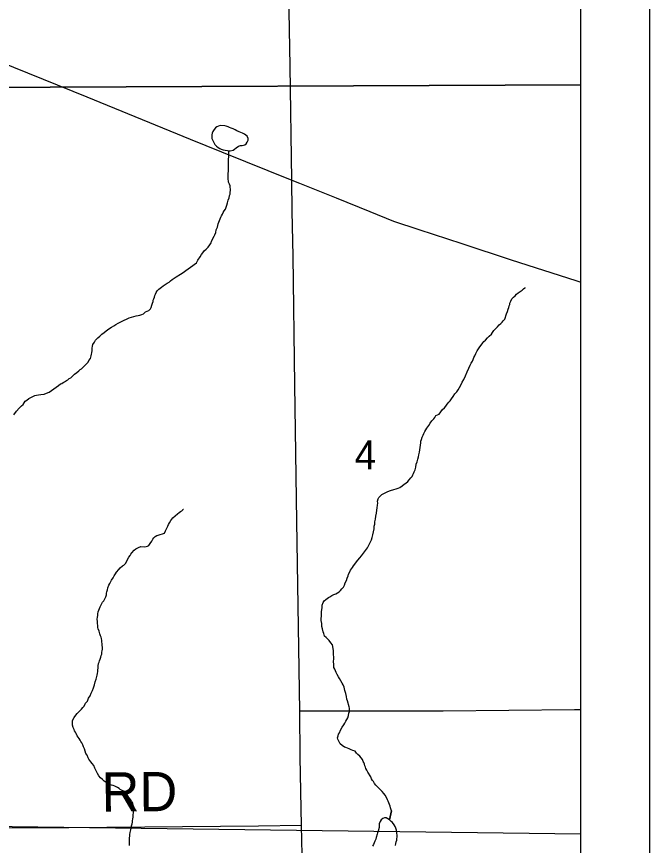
# Model space of a CAD drawing. Extents: x 10.6 to 44.6, y -2.6 to 23.4.
# Drawn here: x 19.186 to 20.103, y 16.584 to 17.784 of the extents above; entities that cross this region are included whole.
import ezdxf

# ---------------------------------------------------------------- set-up
doc = ezdxf.new("R2010")
doc.units = 0
for name, color, linetype in [('GM_X_County', 7, 'Continuous'), ('GM_X_County_Road', 7, 'Continuous'), ('GM_X_Minor_Lake', 7, 'Continuous'), ('GM_X_Minor_River', 7, 'Continuous'), ('GM_X_Section', 7, 'Continuous'), ('GM_X_Section_Text', 7, 'Continuous'), ('GM_X_Township', 7, 'Continuous'), ('GM_X_Township_Road', 7, 'Continuous'), ('GM_X_Township_Road_Text', 7, 'Continuous'), ('GM_X_US_Route', 7, 'Continuous'), ('SH_Data', 7, 'Continuous')]:
    doc.layers.add(name, color=color, linetype=linetype)

msp = doc.modelspace()

# ---------------------------------------------------------------- linework, layer by layer
at = {"layer": 'GM_X_County'}
msp.add_lwpolyline([(20.0033, 15.5302), (20.0033, 22.3267), (13.2033, 22.3267), (13.2033, 15.5267), (19.8413, 15.5267)], dxfattribs=at)
at = {"layer": 'GM_X_County_Road'}
for points in [[(19.5848, 17.5467), (19.5826, 17.712), (19.5792, 17.8983), (19.5753, 18.0763), (19.5711, 18.2524), (19.5677, 18.4449), (19.5648, 18.6461), (19.5616, 18.8476), (19.5588, 19.0263)], [(19.6248, 15.5267), (19.6234, 15.5414), (19.6215, 15.6293), (19.6203, 15.7403), (19.6182, 15.8416), (19.6161, 15.9391), (19.614, 16.0288), (19.6109, 16.1339), (19.6094, 16.1895), (19.6059, 16.3321), (19.6008, 16.5277), (19.5991, 16.6126), (19.5971, 16.7116), (19.5964, 16.7781), (19.5922, 17.0526), (19.589, 17.2507), (19.5866, 17.4368), (19.5856, 17.5019), (19.5848, 17.5467)]]:
    msp.add_lwpolyline(points, dxfattribs=at)
at = {"layer": 'GM_X_Minor_Lake'}
for points in [[(19.481, 17.6263), (19.4765, 17.624), (19.4742, 17.6225), (19.4724, 17.6202), (19.4705, 17.6175), (19.4697, 17.6152), (19.469, 17.6126), (19.469, 17.6085)], [(19.469, 17.6085), (19.469, 17.6072), (19.4698, 17.6053), (19.471, 17.6034), (19.4717, 17.6016), (19.4733, 17.5985), (19.4756, 17.5963), (19.4783, 17.594), (19.4805, 17.5929), (19.4824, 17.5918), (19.4855, 17.5906), (19.4881, 17.5903), (19.4916, 17.5899), (19.4935, 17.5896), (19.4954, 17.5896), (19.4999, 17.5904), (19.5018, 17.5919), (19.5044, 17.5938), (19.5078, 17.5961), (19.5105, 17.5969), (19.5128, 17.5973), (19.5147, 17.5977), (19.5166, 17.5981), (19.5188, 17.5996), (19.5203, 17.6019), (19.5218, 17.6046), (19.5218, 17.6072), (19.5203, 17.6106), (19.5183, 17.6122), (19.5161, 17.6133), (19.5134, 17.6148), (19.5111, 17.6159), (19.5088, 17.617), (19.5054, 17.6185), (19.5027, 17.6196), (19.4997, 17.6211), (19.497, 17.6223), (19.4947, 17.6234), (19.4928, 17.6241), (19.4898, 17.6249), (19.488, 17.6254)], [(19.488, 17.6254), (19.481, 17.6263)], [(19.7349, 16.5837), (19.7353, 16.5864), (19.736, 16.589), (19.7368, 16.5913), (19.7372, 16.5936), (19.7375, 16.5963), (19.7375, 16.599), (19.7371, 16.6012), (19.7371, 16.6035), (19.7363, 16.6058), (19.7355, 16.6089), (19.7344, 16.6111), (19.7332, 16.6138), (19.7309, 16.6168), (19.7286, 16.6187), (19.7263, 16.621), (19.7237, 16.6225), (19.7214, 16.6236), (19.7191, 16.624), (19.7168, 16.6229), (19.7142, 16.6209), (19.7127, 16.6183), (19.7116, 16.6152), (19.7116, 16.6125), (19.7112, 16.6099), (19.7098, 16.6045), (19.709, 16.6022), (19.7086, 16.6), (19.7072, 16.5954), (19.7064, 16.5931), (19.7049, 16.59), (19.7042, 16.5874), (19.7031, 16.5851), (19.7016, 16.5828)]]:
    msp.add_lwpolyline(points, dxfattribs=at)
at = {"layer": 'GM_X_Minor_River'}
for points in [[(19.447, 17.4273), (19.4487, 17.4312), (19.4521, 17.4357), (19.454, 17.4392), (19.4559, 17.4418), (19.4581, 17.4445), (19.4608, 17.4472), (19.4638, 17.4499), (19.466, 17.4533), (19.4679, 17.4564), (19.4687, 17.4583), (19.4705, 17.4625), (19.4724, 17.4659), (19.4735, 17.4678), (19.4746, 17.4712), (19.4754, 17.475), (19.4765, 17.477), (19.4772, 17.4789), (19.4783, 17.4838), (19.482, 17.4933), (19.4832, 17.4952), (19.4843, 17.4975), (19.4854, 17.5002), (19.4869, 17.5025), (19.4888, 17.5048), (19.4899, 17.5078), (19.4906, 17.5109), (19.4918, 17.5139), (19.4929, 17.5181), (19.494, 17.5215), (19.4947, 17.5246), (19.4955, 17.5265), (19.4954, 17.5295), (19.4962, 17.5318), (19.4962, 17.5337), (19.4958, 17.5368), (19.4954, 17.5386), (19.4946, 17.5413), (19.4934, 17.544), (19.493, 17.5462), (19.4926, 17.5481), (19.4935, 17.5896)], [(19.296, 17.3066), (19.2967, 17.3089), (19.2989, 17.3124), (19.3003, 17.3155), (19.3037, 17.3186), (19.3067, 17.3213), (19.3097, 17.3241), (19.313, 17.3264), (19.316, 17.3288), (19.3198, 17.3315), (19.3235, 17.3339), (19.3269, 17.3359), (19.3299, 17.3378), (19.3336, 17.3398), (19.3363, 17.3414), (19.3393, 17.3426), (19.3419, 17.3442), (19.3453, 17.3458), (19.3491, 17.3474), (19.3525, 17.3486), (19.3562, 17.3495), (19.3593, 17.3503), (19.3623, 17.3511), (19.3649, 17.3516), (19.3676, 17.3524), (19.3702, 17.3536), (19.3728, 17.3563), (19.3755, 17.3575), (19.3777, 17.3583), (19.3803, 17.3607), (19.381, 17.3626), (19.3821, 17.366), (19.3832, 17.3691), (19.3839, 17.3714), (19.3842, 17.3733), (19.3849, 17.3752), (19.386, 17.3775), (19.3867, 17.3798), (19.3874, 17.3821), (19.3885, 17.3844), (19.39, 17.3868), (19.3922, 17.3891), (19.3941, 17.3907), (19.396, 17.3922), (19.3986, 17.3938), (19.4016, 17.3958), (19.4042, 17.3977), (19.4072, 17.3993), (19.4094, 17.4013), (19.4117, 17.4032), (19.4147, 17.4052), (19.4173, 17.4068), (19.4196, 17.4084), (19.4214, 17.4092), (19.4237, 17.4107), (19.4259, 17.4123), (19.447, 17.4273)], [(19.7806, 17.188), (19.7821, 17.19), (19.7835, 17.1919), (19.785, 17.1953), (19.7876, 17.1985), (19.7905, 17.2016), (19.792, 17.2035), (19.7935, 17.2062), (19.7961, 17.2074), (19.7984, 17.2082), (19.8032, 17.2148), (19.8062, 17.2175), (19.808, 17.2198), (19.8098, 17.2226), (19.8121, 17.2253), (19.8143, 17.2276), (19.8161, 17.2303), (19.8187, 17.2338), (19.8209, 17.2376), (19.8239, 17.2404), (19.8257, 17.2435), (19.8276, 17.2466), (19.8298, 17.25), (19.8316, 17.2543), (19.8338, 17.2585), (19.8363, 17.2639), (19.8388, 17.2693), (19.8414, 17.2746), (19.8432, 17.2789), (19.8446, 17.282), (19.8465, 17.285), (19.8475, 17.2874), (19.8486, 17.29), (19.8497, 17.2927), (19.8515, 17.2962), (19.8534, 17.2997), (19.8552, 17.3027), (19.857, 17.3055), (19.8589, 17.3082), (19.8614, 17.3116), (19.8629, 17.3136), (19.8652, 17.3152), (19.8681, 17.3186), (19.8707, 17.321), (19.8741, 17.3241), (19.8756, 17.3264), (19.8774, 17.3291), (19.8793, 17.3311), (19.8826, 17.3346), (19.8852, 17.3377), (19.8878, 17.3396), (19.8897, 17.3412), (19.8912, 17.3431), (19.8934, 17.3459), (19.8959, 17.3535), (19.8973, 17.357), (19.898, 17.3604), (19.8991, 17.3627), (19.8998, 17.365), (19.9005, 17.367), (19.9008, 17.3689), (19.9023, 17.3719), (19.9037, 17.375), (19.906, 17.3774), (19.9082, 17.3797), (19.9104, 17.382), (19.9127, 17.384), (19.9157, 17.3859), (19.9183, 17.3875), (19.9205, 17.3895), (19.9224, 17.391), (19.9232, 17.3915)], [(19.1822, 17.2074), (19.1863, 17.2124), (19.19, 17.2167), (19.1934, 17.2202), (19.1956, 17.2221), (19.1971, 17.2245), (19.1989, 17.2268), (19.2012, 17.2284), (19.2038, 17.2307), (19.2109, 17.2343), (19.2128, 17.2351), (19.2151, 17.2355), (19.2181, 17.236), (19.2215, 17.2364), (19.2264, 17.2373), (19.2294, 17.2385), (19.2332, 17.2401), (19.2366, 17.2425), (19.2403, 17.2448), (19.2437, 17.2472), (19.2471, 17.2499), (19.2497, 17.2519), (19.2519, 17.2527), (19.2538, 17.2539), (19.2557, 17.2551), (19.2583, 17.2567), (19.2606, 17.2579), (19.2624, 17.2598), (19.2647, 17.261), (19.2677, 17.2637), (19.2703, 17.2661), (19.2733, 17.2684), (19.2763, 17.2708), (19.2785, 17.2727), (19.2804, 17.2739), (19.2841, 17.2778), (19.2859, 17.2797), (19.2878, 17.2817), (19.2897, 17.2836), (19.2911, 17.2859), (19.2933, 17.2887), (19.2937, 17.2906), (19.2944, 17.2925), (19.2947, 17.2948), (19.2954, 17.2971), (19.2957, 17.3001), (19.2957, 17.302), (19.2957, 17.3039), (19.296, 17.3066)], [(19.6294, 16.8972), (19.6285, 16.901), (19.6281, 16.9052), (19.6276, 16.9094), (19.6275, 16.9124), (19.6278, 16.9158), (19.628, 16.9227), (19.6284, 16.925), (19.6287, 16.9284), (19.629, 16.9319), (19.6304, 16.9353), (19.6319, 16.938), (19.6341, 16.94), (19.636, 16.9411), (19.6382, 16.9427), (19.6401, 16.9439), (19.6427, 16.9455), (19.6457, 16.9471), (19.6484, 16.9483), (19.651, 16.9495), (19.6533, 16.9511), (19.6555, 16.953), (19.6573, 16.9553), (19.6596, 16.9577), (19.661, 16.9604), (19.6621, 16.9638), (19.6639, 16.9673), (19.665, 16.9707), (19.6664, 16.9742), (19.6671, 16.9765), (19.669, 16.98), (19.67, 16.9823), (19.6711, 16.9842), (19.6726, 16.9861), (19.6741, 16.9884), (19.6759, 16.9908), (19.6785, 16.9943), (19.6807, 16.997), (19.6833, 17.0001), (19.6859, 17.0032), (19.6889, 17.007), (19.6914, 17.0109), (19.6944, 17.0148), (19.6966, 17.0186), (19.6984, 17.0225), (19.7002, 17.0263), (19.7013, 17.0298), (19.7023, 17.0336), (19.704, 17.0424), (19.7043, 17.0458), (19.705, 17.0489), (19.7053, 17.0523), (19.706, 17.0562), (19.7067, 17.0607), (19.7073, 17.0649), (19.708, 17.0691), (19.7087, 17.0726), (19.709, 17.0764), (19.7093, 17.0795), (19.7092, 17.0821), (19.7099, 17.0856), (19.711, 17.0875), (19.7132, 17.0898), (19.7151, 17.0918), (19.717, 17.0929), (19.7203, 17.0945), (19.7237, 17.0961), (19.7279, 17.0978), (19.7324, 17.099), (19.7362, 17.1002), (19.7388, 17.1011), (19.7411, 17.1022), (19.7445, 17.1042), (19.7478, 17.1066), (19.7501, 17.1085), (19.7527, 17.1109), (19.7549, 17.1132), (19.7571, 17.1159), (19.759, 17.1179), (19.7601, 17.1202), (19.7612, 17.1221), (19.7623, 17.1248), (19.7633, 17.1275), (19.7644, 17.1313), (19.765, 17.1359), (19.7665, 17.1394), (19.7672, 17.1428), (19.7682, 17.1462), (19.7689, 17.1493), (19.7696, 17.1531), (19.7703, 17.1566), (19.7713, 17.1634), (19.7716, 17.1665), (19.7719, 17.1692), (19.7726, 17.1715), (19.7737, 17.1749), (19.7751, 17.178), (19.7762, 17.1803), (19.7777, 17.183), (19.7791, 17.1853), (19.7806, 17.188)], [(19.3797, 17.0211), (19.3819, 17.0242), (19.3838, 17.0273), (19.3848, 17.0292), (19.3871, 17.0311), (19.3893, 17.0323), (19.3912, 17.0328), (19.4007, 17.036), (19.4021, 17.0391), (19.4028, 17.041), (19.4039, 17.0429), (19.4054, 17.046), (19.4065, 17.0483), (19.4075, 17.051), (19.4098, 17.0541), (19.4127, 17.058), (19.4157, 17.0611), (19.4194, 17.0638), (19.4217, 17.0658), (19.4235, 17.0674), (19.4254, 17.0682), (19.4273, 17.0701), (19.4276, 17.0705), (19.428, 17.0705)], [(19.2695, 16.7518), (19.2683, 16.7548), (19.2674, 16.7578), (19.2673, 16.7627), (19.2673, 16.7646), (19.2698, 16.7689), (19.272, 16.7724), (19.2739, 16.7747), (19.2761, 16.777), (19.2784, 16.779), (19.2802, 16.7813), (19.2821, 16.7833), (19.2839, 16.7856), (19.2861, 16.7898), (19.2891, 16.7929), (19.2905, 16.7971), (19.2927, 16.8006), (19.2945, 16.8045), (19.2963, 16.8083), (19.2978, 16.8122), (19.2992, 16.8164), (19.3002, 16.8206), (19.3013, 16.8244), (19.3023, 16.8282), (19.303, 16.8302), (19.3034, 16.8328), (19.3037, 16.8355), (19.304, 16.8378), (19.3043, 16.8409), (19.3046, 16.8439), (19.3049, 16.847), (19.3057, 16.8493), (19.3064, 16.8512), (19.3075, 16.8535), (19.3082, 16.8562), (19.3089, 16.8588), (19.3096, 16.8608), (19.3099, 16.8634), (19.3102, 16.8657), (19.3106, 16.868), (19.3104, 16.8764), (19.3099, 16.8783), (19.3095, 16.8806), (19.3091, 16.8832), (19.3086, 16.8851), (19.3078, 16.8874), (19.3066, 16.8904), (19.3062, 16.8923), (19.3058, 16.8942), (19.3046, 16.8976), (19.3041, 16.8995), (19.3037, 16.9025), (19.3032, 16.9048), (19.3032, 16.9082), (19.3031, 16.9112), (19.3034, 16.9143), (19.3037, 16.9166), (19.3041, 16.9189), (19.3044, 16.9219), (19.3055, 16.9246), (19.3062, 16.9269), (19.3073, 16.9292), (19.3087, 16.9323), (19.3109, 16.9358), (19.3124, 16.9377), (19.3135, 16.9397), (19.3146, 16.942), (19.3153, 16.9439), (19.3164, 16.9466), (19.3167, 16.9489), (19.317, 16.9511), (19.3177, 16.9538), (19.3184, 16.9569), (19.3198, 16.9607), (19.3213, 16.963), (19.3239, 16.9677), (19.3261, 16.9711), (19.3275, 16.9742), (19.3294, 16.9769), (19.3308, 16.9796), (19.3342, 16.9835), (19.3364, 16.9858), (19.3398, 16.9886), (19.3416, 16.9898), (19.3439, 16.9921), (19.3461, 16.9952), (19.3471, 16.9979), (19.349, 17.001), (19.3508, 17.0037), (19.3519, 17.0056), (19.353, 17.0075), (19.3567, 17.0114), (19.359, 17.013), (19.3608, 17.0142), (19.3627, 17.015), (19.3661, 17.0166), (19.3714, 17.0163), (19.3741, 17.0168), (19.376, 17.0172), (19.3779, 17.018), (19.3797, 17.0211)], [(19.729, 16.6339), (19.7263, 16.621), (19.729, 16.6341), (19.7277, 16.6383), (19.7273, 16.6409), (19.7265, 16.6432), (19.7256, 16.6455), (19.7245, 16.6477), (19.7236, 16.65), (19.7221, 16.653), (19.7201, 16.6564), (19.7181, 16.659), (19.7158, 16.662), (19.713, 16.665), (19.7103, 16.6672), (19.7084, 16.6691), (19.7064, 16.6713), (19.7048, 16.6736), (19.7033, 16.6762), (19.7017, 16.678), (19.7005, 16.6803), (19.6993, 16.6833), (19.695, 16.6901), (19.6934, 16.6927), (19.6922, 16.695), (19.6914, 16.6972), (19.6906, 16.6991), (19.6901, 16.7014), (19.6893, 16.7037), (19.6881, 16.7055), (19.6873, 16.7082), (19.6854, 16.7108), (19.6834, 16.713), (19.6807, 16.7156), (19.6787, 16.7175), (19.6764, 16.7201), (19.673, 16.7212), (19.6706, 16.7223), (19.668, 16.7237), (19.6653, 16.7248), (19.663, 16.7255), (19.661, 16.7262), (19.6576, 16.7285), (19.6549, 16.7311), (19.6537, 16.7329), (19.6525, 16.7356), (19.6513, 16.7378), (19.6512, 16.7397), (19.6519, 16.7424), (19.6526, 16.7447), (19.6537, 16.747), (19.6552, 16.7505), (19.6577, 16.7551), (19.6603, 16.7582), (19.6618, 16.7609), (19.6632, 16.7636), (19.6647, 16.7663), (19.6658, 16.7686), (19.6669, 16.7717), (19.6675, 16.7751), (19.6682, 16.7778), (19.6686, 16.7801), (19.6685, 16.7824), (19.6681, 16.7843), (19.6656, 16.793), (19.6644, 16.7956), (19.6639, 16.7994), (19.6631, 16.8036), (19.6618, 16.8081), (19.6606, 16.813), (19.6594, 16.8164), (19.6578, 16.8187), (19.6558, 16.8221), (19.6538, 16.8254), (19.6523, 16.8281), (19.6507, 16.8315), (19.6491, 16.8341), (19.6479, 16.8367), (19.6471, 16.839), (19.6459, 16.8416), (19.6458, 16.8435), (19.6458, 16.8458), (19.6453, 16.85), (19.6456, 16.8542), (19.6455, 16.8569), (19.6454, 16.8599), (19.6454, 16.8618), (19.6454, 16.8637), (19.6453, 16.866), (19.6449, 16.8686), (19.6444, 16.8717), (19.6436, 16.8743), (19.6416, 16.8773), (19.6389, 16.8807), (19.6369, 16.8822), (19.6346, 16.8848), (19.6323, 16.887), (19.631, 16.8908), (19.6302, 16.8931), (19.6294, 16.8972)], [(19.3498, 16.5838), (19.3497, 16.588), (19.35, 16.5914), (19.3499, 16.5944), (19.3502, 16.5975), (19.3505, 16.5998), (19.3508, 16.6024), (19.3512, 16.6044), (19.3515, 16.6063), (19.3522, 16.6089), (19.3529, 16.612), (19.3536, 16.6151), (19.3539, 16.6177), (19.3542, 16.62), (19.3546, 16.6219), (19.3549, 16.6254), (19.3552, 16.6288), (19.3555, 16.6307), (19.3558, 16.6338), (19.3561, 16.6368), (19.3561, 16.6395), (19.3553, 16.6421), (19.3544, 16.6452), (19.3525, 16.6478), (19.3517, 16.6497), (19.3489, 16.653), (19.3477, 16.6553), (19.3462, 16.6572), (19.3438, 16.6601), (19.3411, 16.6624), (19.3365, 16.6649), (19.3346, 16.6664), (19.3326, 16.6675), (19.3303, 16.6686), (19.3284, 16.6697), (19.3261, 16.6704), (19.3238, 16.6711), (19.3215, 16.6722), (19.3188, 16.6733), (19.3161, 16.6751), (19.313, 16.677), (19.3107, 16.6792), (19.3076, 16.6818), (19.3056, 16.6848), (19.3036, 16.6882), (19.3016, 16.6916), (19.2997, 16.6957), (19.298, 16.6995), (19.2957, 16.7025), (19.2937, 16.7047), (19.2922, 16.7066), (19.291, 16.7085), (19.2898, 16.7107), (19.2886, 16.7145), (19.2866, 16.7171), (19.2858, 16.7205), (19.2846, 16.7235), (19.2834, 16.7266), (19.2821, 16.7296), (19.2806, 16.7322), (19.2794, 16.7345), (19.2782, 16.7363), (19.277, 16.7386), (19.2754, 16.7405), (19.2742, 16.7427), (19.2726, 16.7457), (19.2715, 16.748), (19.2703, 16.7499), (19.2695, 16.7518)]]:
    msp.add_lwpolyline(points, dxfattribs=at)
at = {"layer": 'GM_X_Section'}
for p, q in [((20.0033, 17.685), (20.0033, 18.797)), ((20.0033, 16.6008), (20.0033, 17.685))]:
    msp.add_line(p, q, dxfattribs=at)
for points in [[(20.0033, 18.797), (19.1006, 18.7791), (19.125, 17.681), (20.0033, 17.685)], [(20.0033, 17.685), (19.125, 17.681), (19.1418, 16.6213), (19.1419, 16.6144), (19.1419, 16.6116), (20.0033, 16.6008)]]:
    msp.add_lwpolyline(points, dxfattribs=at)
at = {"layer": 'GM_X_Township'}
msp.add_line((20.0033, 15.5302), (20.0033, 20.9573), dxfattribs=at)
at = {"layer": 'GM_X_Township_Road'}
for points in [[(20.0033, 16.78), (19.9945, 16.7801), (19.8043, 16.7783), (19.6825, 16.7783), (19.5964, 16.7781)], [(19.5991, 16.6126), (19.5366, 16.6119), (19.2619, 16.6095), (18.9861, 16.6077), (18.7284, 16.6054), (18.6038, 16.6042), (18.5905, 16.6049), (18.4954, 16.6035), (18.4056, 16.6021), (18.3128, 16.6014), (18.2258, 16.6007), (18.107, 16.5993), (18.0035, 16.5982), (17.9186, 16.5972), (17.821, 16.5964), (17.788, 16.5964)]]:
    msp.add_lwpolyline(points, dxfattribs=at)
at = {"layer": 'GM_X_US_Route'}
for points in [[(18.6315, 17.9333), (18.762, 17.8801), (19.0322, 17.771), (19.2878, 17.6674), (19.4378, 17.6063), (19.483, 17.588)], [(19.483, 17.588), (19.5848, 17.5467), (19.5959, 17.5424), (19.649, 17.5212), (19.6979, 17.5015), (19.7323, 17.4876), (19.7686, 17.4753), (19.8309, 17.4553), (19.9026, 17.4318), (19.9963, 17.4016), (20.0033, 17.3993)]]:
    msp.add_lwpolyline(points, dxfattribs=at)
at = {"layer": 'SH_Data'}
msp.add_line((20.1028, 22.4265), (20.1028, 15.4265), dxfattribs=at)

# ---------------------------------------------------------------- texts
at = {"layer": 'GM_X_Section_Text'}
msp.add_text('4', height=0.0419, rotation=0, dxfattribs=at).set_placement((19.6759, 17.1283))
at = {"layer": 'GM_X_Township_Road_Text'}
msp.add_text('RD', height=0.05682, rotation=0.4936, dxfattribs=at).set_placement((19.3095, 16.6327))

doc.saveas('drawing.dxf')
